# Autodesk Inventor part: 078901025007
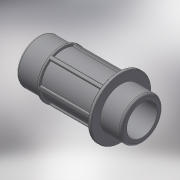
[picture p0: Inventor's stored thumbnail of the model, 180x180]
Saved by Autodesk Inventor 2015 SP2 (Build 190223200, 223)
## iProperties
Created: 2018-02
Part Number: 078901025007
Material: Generic
Description: PLASSON THREADED MALE ADAPTOR 25-3/4"
Document SubType Name: Modeling
Designer: KIM
Density: 1 g/cm^3
Appearance: Default
Author: KIM
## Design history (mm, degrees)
derived "078901.ipt"
feature "Solid1::078901.ipt"
tag "TaggingFeature1"
body "Solid1"
other parameters: "d4" = 1.32205, "d14" = 2.11528, "d15" = 1.05764, "d17" = 0, "d20" = 360 deg, "d40" = 18, "d41" = 26.441, "d45" = 29.0851, "d46" = 18.5087, "d47" = 1.8, "d78" = 25, "d85" = 0.26441, "d91" = 16, "d103" = 18.4, "d104" = 37, "d105" = 0.26441, "R_" = 26.441, "E_" = 37, "l_2" = 18, "d_" = 25
